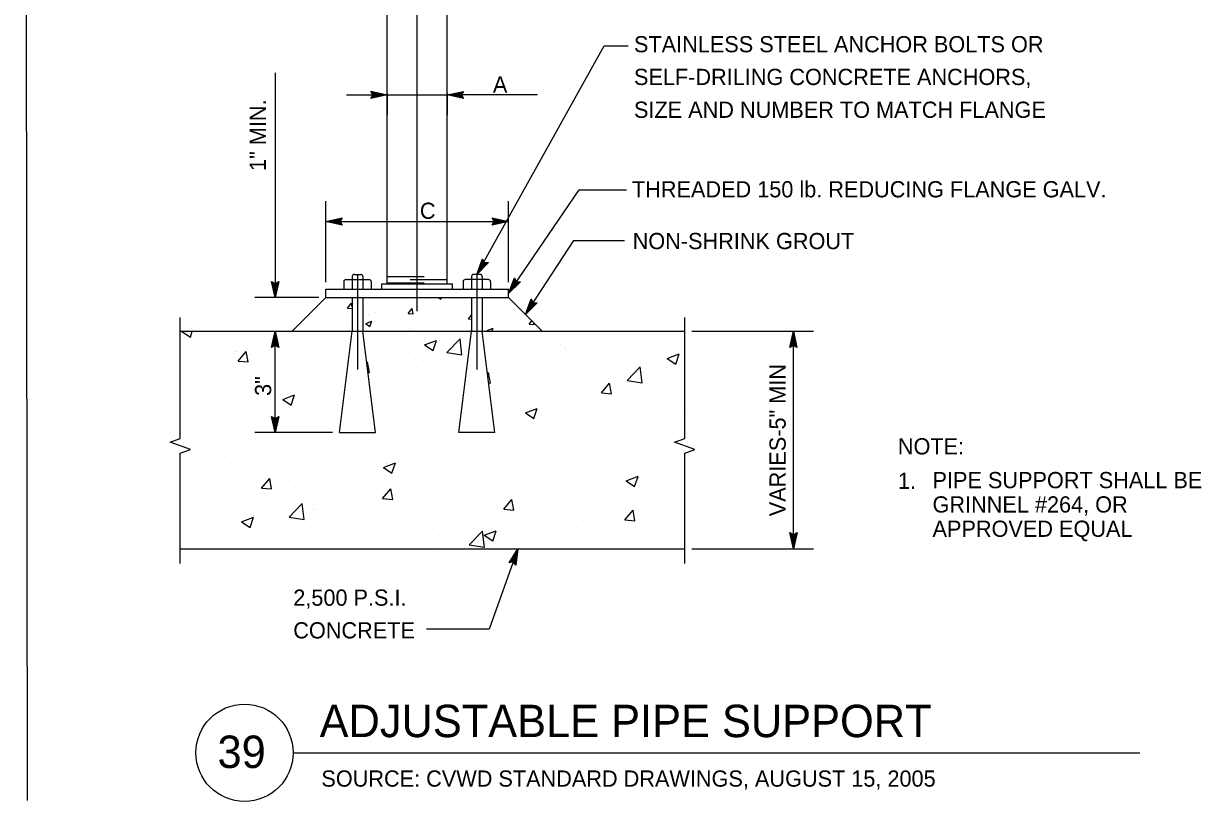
# Model space of a CAD drawing. Extents: x -121933 to -117742, y -103160 to -100084.
# Drawn here: x -121211 to -120775, y -102136.5 to -101848.5 of the extents above; entities that cross this region are included whole.
import ezdxf

# ---------------------------------------------------------------- set-up
doc = ezdxf.new("R2010")
doc.units = 0
for name, color, linetype in [('G-MARK', 7, 'Continuous'), ('G-TEXT', 7, 'Continuous'), ('Misc CnstDet(22)', 7, 'Continuous')]:
    doc.layers.add(name, color=color, linetype=linetype)

msp = doc.modelspace()

# ---------------------------------------------------------------- linework, layer by layer
at = {"layer": 'G-MARK'}
for p, q in [((-121117.88, -101866.71), (-121117.88, -101949.94)), ((-121091.47, -101874.94), (-121076.47, -101874.94)), ((-121020.77, -101874.94), (-121054.2, -101874.94)), ((-121099.13, -101944.19), (-121099.13, -101914.32)), ((-121031.55, -101944.19), (-121031.55, -101914.32)), ((-121099.13, -101921.82), (-121031.55, -101921.82)), ((-121101.75, -101949.94), (-121125.38, -101949.94)), ((-121117.88, -101999.94), (-121117.88, -101962.44)), ((-120963.69, -101962.44), (-120918.58, -101962.44)), ((-120926.08, -102042.91), (-120926.08, -101962.44)), ((-121096.67, -101999.94), (-121125.38, -101999.94)), ((-120963.69, -102042.91), (-120918.58, -102042.91))]:
    msp.add_line(p, q, dxfattribs=at)
for points in [[(-121043.27, -101941.35), (-120996.14, -101856.81), (-120987.23, -101856.81)], [(-121031.55, -101948.38), (-121005.38, -101910.1), (-120987.8, -101910.1)], [(-121025.3, -101956.19), (-121007.33, -101928.85), (-120988.58, -101928.85)], [(-121028.03, -102042.91), (-121038.74, -102072.63), (-121061.92, -102072.65)]]:
    msp.add_lwpolyline(points, dxfattribs=at)
at = {"layer": 'G-TEXT'}
for p, q in [((-121081.67, -101874.94), (-121082.47, -101873.6)), ((-121082.47, -101873.6), (-121082.47, -101873.6)), ((-121082.47, -101873.6), (-121076.47, -101874.94)), ((-121076.47, -101874.94), (-121082.47, -101876.27)), ((-121082.47, -101876.27), (-121081.67, -101874.94)), ((-121082.47, -101876.27), (-121082.47, -101876.27)), ((-121082.25, -101873.96), (-121077.85, -101874.94)), ((-121077.86, -101874.95), (-121082.24, -101875.91)), ((-121079.23, -101874.94), (-121082.06, -101875.57)), ((-121082.02, -101874.32), (-121079.23, -101874.94)), ((-121081.84, -101874.67), (-121080.61, -101874.94)), ((-121080.61, -101874.94), (-121081.82, -101875.21)), ((-121076.47, -101874.94), (-121076.47, -101874.94)), ((-121054.2, -101874.94), (-121048.2, -101873.61)), ((-121048.2, -101876.28), (-121054.2, -101874.94)), ((-121054.2, -101874.94), (-121054.2, -101874.94)), ((-121048.42, -101875.93), (-121052.82, -101874.94)), ((-121052.81, -101874.94), (-121048.44, -101873.97)), ((-121051.44, -101874.95), (-121048.62, -101874.32)), ((-121048.65, -101875.57), (-121051.44, -101874.95)), ((-121050.06, -101874.95), (-121048.85, -101874.68)), ((-121048.83, -101875.22), (-121050.06, -101874.95)), ((-121048.2, -101873.61), (-121049, -101874.94)), ((-121049, -101874.94), (-121048.2, -101876.28)), ((-121048.2, -101873.61), (-121048.2, -101873.61)), ((-121048.2, -101876.28), (-121048.2, -101876.28)), ((-121099.13, -101921.82), (-121093.13, -101920.49)), ((-121093.13, -101923.16), (-121099.13, -101921.82)), ((-121099.13, -101921.82), (-121099.13, -101921.82)), ((-121093.34, -101922.8), (-121097.75, -101921.82)), ((-121097.74, -101921.82), (-121093.36, -101920.85)), ((-121096.36, -101921.82), (-121093.54, -101921.19)), ((-121093.58, -101922.44), (-121096.36, -101921.82)), ((-121094.98, -101921.82), (-121093.77, -101921.55)), ((-121093.75, -101922.1), (-121094.98, -101921.82)), ((-121093.13, -101920.49), (-121093.93, -101921.82)), ((-121093.93, -101921.82), (-121093.13, -101923.16)), ((-121093.13, -101920.49), (-121093.13, -101920.49)), ((-121093.13, -101923.16), (-121093.13, -101923.16)), ((-121036.75, -101921.82), (-121037.55, -101920.48)), ((-121037.55, -101920.48), (-121037.55, -101920.48)), ((-121037.55, -101920.48), (-121031.55, -101921.82)), ((-121031.55, -101921.82), (-121037.55, -101923.15)), ((-121037.55, -101923.15), (-121036.75, -101921.82)), ((-121037.55, -101923.15), (-121037.55, -101923.15)), ((-121037.33, -101920.83), (-121032.93, -101921.82)), ((-121032.94, -101921.82), (-121037.31, -101922.79)), ((-121034.31, -101921.82), (-121037.14, -101922.44)), ((-121037.1, -101921.19), (-121034.31, -101921.82)), ((-121036.92, -101921.54), (-121035.69, -101921.82)), ((-121035.69, -101921.82), (-121036.9, -101922.08)), ((-121031.55, -101921.82), (-121031.55, -101921.82)), ((-121043.27, -101941.35), (-121041.17, -101935.57)), ((-121038.92, -101937.01), (-121043.27, -101941.35)), ((-121039.33, -101937), (-121042.53, -101940.19)), ((-121042.52, -101940.17), (-121040.99, -101935.96)), ((-121041.78, -101939.02), (-121040.8, -101936.3)), ((-121039.76, -101937), (-121041.78, -101939.02)), ((-121041.17, -101935.57), (-121041.17, -101935.57)), ((-121041.17, -101935.57), (-121040.48, -101936.96)), ((-121041.04, -101937.85), (-121040.62, -101936.69)), ((-121040.15, -101936.96), (-121041.04, -101937.85)), ((-121040.48, -101936.96), (-121038.92, -101937.01)), ((-121038.92, -101937.01), (-121038.92, -101937.01)), ((-121043.27, -101941.35), (-121043.27, -101941.35)), ((-121117.88, -101949.94), (-121119.21, -101943.94)), ((-121119.21, -101943.94), (-121119.21, -101943.94)), ((-121119.21, -101943.94), (-121117.88, -101944.74)), ((-121117.88, -101948.55), (-121118.85, -101944.18)), ((-121117.87, -101947.18), (-121118.5, -101944.36)), ((-121117.87, -101945.8), (-121118.14, -101944.59)), ((-121117.88, -101944.74), (-121116.54, -101943.94)), ((-121116.54, -101943.94), (-121117.88, -101949.94)), ((-121116.89, -101944.16), (-121117.88, -101948.56)), ((-121117.25, -101944.39), (-121117.87, -101947.18)), ((-121117.6, -101944.57), (-121117.87, -101945.8)), ((-121116.54, -101943.94), (-121116.54, -101943.94)), ((-121031.55, -101948.38), (-121029.26, -101942.68)), ((-121027.06, -101944.18), (-121031.55, -101948.38)), ((-121030.77, -101947.23), (-121029.1, -101943.07)), ((-121027.47, -101944.16), (-121030.77, -101947.24)), ((-121029.99, -101946.1), (-121028.91, -101943.42)), ((-121027.9, -101944.15), (-121029.99, -101946.1)), ((-121029.26, -101942.68), (-121029.26, -101942.68)), ((-121029.26, -101942.68), (-121028.61, -101944.09)), ((-121029.21, -101944.96), (-121028.75, -101943.81)), ((-121028.29, -101944.1), (-121029.21, -101944.96)), ((-121028.61, -101944.09), (-121027.06, -101944.18)), ((-121027.06, -101944.18), (-121027.06, -101944.18)), ((-121117.88, -101949.94), (-121117.88, -101949.94)), ((-121031.55, -101948.38), (-121031.55, -101948.38)), ((-121025.3, -101956.19), (-121023.14, -101950.44)), ((-121023.14, -101950.44), (-121023.14, -101950.44)), ((-121023.14, -101950.44), (-121022.46, -101951.84)), ((-121020.9, -101951.9), (-121025.3, -101956.19)), ((-121024.54, -101955.03), (-121022.97, -101950.83)), ((-121021.32, -101951.88), (-121024.54, -101955.04)), ((-121023.79, -101953.88), (-121022.77, -101951.17)), ((-121021.75, -101951.88), (-121023.79, -101953.88)), ((-121023.03, -101952.72), (-121022.6, -101951.56)), ((-121022.13, -101951.84), (-121023.03, -101952.72)), ((-121022.46, -101951.84), (-121020.9, -101951.9)), ((-121020.9, -101951.9), (-121020.9, -101951.9)), ((-121025.3, -101956.19), (-121025.3, -101956.19)), ((-121119.22, -101968.44), (-121117.88, -101962.44)), ((-121118.86, -101968.23), (-121117.88, -101963.82)), ((-121117.88, -101962.44), (-121117.88, -101962.44)), ((-121117.88, -101962.44), (-121116.55, -101968.44)), ((-121117.87, -101963.83), (-121116.91, -101968.21)), ((-120927.42, -101968.44), (-120926.08, -101962.44)), ((-120927.06, -101968.23), (-120926.08, -101963.82)), ((-120926.08, -101962.44), (-120926.08, -101962.44)), ((-120926.08, -101962.44), (-120924.75, -101968.44)), ((-120926.08, -101963.83), (-120925.11, -101968.21)), ((-121117.88, -101967.64), (-121119.22, -101968.44)), ((-121118.5, -101967.99), (-121117.88, -101965.21)), ((-121118.15, -101967.82), (-121117.88, -101966.59)), ((-121117.88, -101965.21), (-121117.25, -101968.03)), ((-121117.88, -101966.59), (-121117.61, -101967.8)), ((-121116.55, -101968.44), (-121117.88, -101967.64)), ((-120926.08, -101967.64), (-120927.42, -101968.44)), ((-120926.7, -101967.99), (-120926.08, -101965.21)), ((-120926.36, -101967.82), (-120926.08, -101966.59)), ((-120926.08, -101965.21), (-120925.46, -101968.03)), ((-120926.08, -101966.59), (-120925.81, -101967.8)), ((-120924.75, -101968.44), (-120926.08, -101967.64)), ((-121119.22, -101968.44), (-121119.22, -101968.44)), ((-121116.55, -101968.44), (-121116.55, -101968.44)), ((-120927.42, -101968.44), (-120927.42, -101968.44)), ((-120924.75, -101968.44), (-120924.75, -101968.44)), ((-121117.88, -101999.94), (-121119.21, -101993.94)), ((-121119.21, -101993.94), (-121119.21, -101993.94)), ((-121119.21, -101993.94), (-121117.88, -101994.74)), ((-121117.88, -101998.55), (-121118.85, -101994.18)), ((-121117.87, -101997.18), (-121118.5, -101994.36)), ((-121117.88, -101994.74), (-121116.54, -101993.94)), ((-121116.54, -101993.94), (-121117.88, -101999.94)), ((-121116.89, -101994.16), (-121117.88, -101998.56)), ((-121116.54, -101993.94), (-121116.54, -101993.94)), ((-121117.87, -101995.8), (-121118.14, -101994.59)), ((-121117.25, -101994.39), (-121117.87, -101997.18)), ((-121117.6, -101994.57), (-121117.87, -101995.8)), ((-121117.88, -101999.94), (-121117.88, -101999.94)), ((-120926.08, -102042.91), (-120927.41, -102036.91)), ((-120927.41, -102036.91), (-120927.41, -102036.91)), ((-120927.41, -102036.91), (-120926.08, -102037.71)), ((-120926.08, -102041.52), (-120927.05, -102037.15)), ((-120926.08, -102040.15), (-120926.7, -102037.32)), ((-120926.08, -102038.77), (-120926.34, -102037.56)), ((-120926.08, -102037.71), (-120924.74, -102036.91)), ((-120924.74, -102036.91), (-120926.08, -102042.91)), ((-120925.1, -102037.13), (-120926.08, -102041.53)), ((-120925.46, -102037.36), (-120926.08, -102040.15)), ((-120925.8, -102037.54), (-120926.08, -102038.77)), ((-120924.74, -102036.91), (-120924.74, -102036.91)), ((-121031.32, -102048.11), (-121028.03, -102042.91)), ((-121030.91, -102048.02), (-121028.5, -102044.21)), ((-121030.49, -102047.93), (-121028.97, -102045.51)), ((-121028.97, -102045.51), (-121029.33, -102048.38)), ((-121028.5, -102044.22), (-121029.07, -102048.67)), ((-121028.03, -102042.91), (-121028.81, -102049.01)), ((-121028.03, -102042.91), (-121028.03, -102042.91)), ((-120926.08, -102042.91), (-120926.08, -102042.91)), ((-121029.79, -102047.81), (-121031.32, -102048.11)), ((-121031.32, -102048.11), (-121031.32, -102048.11)), ((-121030.11, -102047.88), (-121029.44, -102046.81)), ((-121028.81, -102049.01), (-121029.79, -102047.81)), ((-121029.44, -102046.81), (-121029.59, -102048.04)), ((-121028.81, -102049.01), (-121028.81, -102049.01))]:
    msp.add_line(p, q, dxfattribs=at)
at = {"layer": 'Misc CnstDet(22)'}
for p, q in [((-121211.03, -101153.11), (-121209.67, -102136.14)), ((-121065.34, -101955.02), (-121065.34, -101695.26)), ((-121076.47, -101944.87), (-121076.47, -101832.76)), ((-121054.2, -101944.87), (-121054.2, -101832.76)), ((-121076.47, -101874.44), (-121076.47, -101882.44)), ((-121076.47, -101874.94), (-121054.2, -101874.94)), ((-121054.2, -101874.44), (-121054.2, -101882.44)), ((-121088.58, -101941.35), (-121086.24, -101941.35)), ((-121087.41, -101941.35), (-121087.41, -101976.51)), ((-121042.1, -101941.35), (-121044.44, -101941.35)), ((-121043.27, -101941.35), (-121043.27, -101976.51)), ((-121092.49, -101944.08), (-121092.49, -101946.82)), ((-121091.7, -101943.3), (-121083.11, -101943.3)), ((-121089.36, -101942.13), (-121089.36, -101946.82)), ((-121085.45, -101942.13), (-121085.45, -101946.82)), ((-121082.33, -101944.08), (-121082.33, -101946.82)), ((-121078.42, -101944.87), (-121052.25, -101944.87)), ((-121078.42, -101946.82), (-121078.42, -101944.87)), ((-121076.47, -101942.13), (-121062.8, -101942.13)), ((-121076.47, -101944.48), (-121062.8, -101944.48)), ((-121067.88, -101943.3), (-121054.2, -101943.3)), ((-121052.25, -101946.82), (-121052.25, -101944.87)), ((-121048.35, -101944.08), (-121048.35, -101946.82)), ((-121038.97, -101943.3), (-121047.56, -101943.3)), ((-121045.22, -101942.13), (-121045.22, -101946.82)), ((-121041.31, -101942.13), (-121041.31, -101946.82)), ((-121038.19, -101944.08), (-121038.19, -101946.82)), ((-121111.63, -101962.44), (-121099.13, -101949.94)), ((-121099.13, -101946.82), (-121031.55, -101946.82)), ((-121099.13, -101949.94), (-121099.13, -101946.82)), ((-121099.13, -101949.94), (-121031.55, -101949.94)), ((-121089.36, -101949.94), (-121089.36, -101962.44)), ((-121085.45, -101949.94), (-121085.45, -101962.44)), ((-121057.44, -101949.94), (-121056.55, -101950.54)), ((-121056.55, -101950.55), (-121056.34, -101949.94)), ((-121046.87, -101950.12), (-121046.87, -101950.12)), ((-121045.22, -101949.94), (-121045.22, -101962.44)), ((-121041.31, -101949.94), (-121041.31, -101962.44)), ((-121041.26, -101950.26), (-121041.26, -101950.26)), ((-121031.55, -101949.94), (-121031.55, -101946.82)), ((-121019.05, -101962.44), (-121031.55, -101949.94)), ((-121100.1, -101955.07), (-121100.1, -101955.07)), ((-121091.12, -101953.86), (-121089.61, -101952.07)), ((-121091.12, -101953.86), (-121089.36, -101954.02)), ((-121089.36, -101953.41), (-121089.61, -101952.07)), ((-121084.06, -101952.87), (-121084.06, -101952.87)), ((-121072.83, -101954.41), (-121072.83, -101954.41)), ((-121068.7, -101955.82), (-121067.19, -101954.03)), ((-121068.27, -101950.87), (-121068.27, -101950.87)), ((-121066.83, -101955.99), (-121067.19, -101954.03)), ((-121065.09, -101953.25), (-121065.09, -101953.25)), ((-121061, -101952.86), (-121061, -101952.86)), ((-121101.54, -101959.5), (-121101.54, -101959.5)), ((-121100.39, -101958.04), (-121100.39, -101958.04)), ((-121084.36, -101959.57), (-121082.17, -101958.73)), ((-121083.32, -101956.37), (-121083.32, -101956.37)), ((-121082.8, -101960.63), (-121082.17, -101958.74)), ((-121080.65, -101955.44), (-121080.65, -101955.44)), ((-121068.7, -101955.82), (-121066.83, -101955.99)), ((-121052.42, -101958.93), (-121052.42, -101958.93)), ((-121046.29, -101957.78), (-121045.22, -101956.51)), ((-121046.29, -101957.78), (-121045.22, -101957.88)), ((-121036.38, -101956.73), (-121036.38, -101956.73)), ((-121023.87, -101959.74), (-121022.9, -101958.59)), ((-121022, -101959.92), (-121022.1, -101959.39)), ((-121153.03, -101962.44), (-120966.31, -101962.44)), ((-121152.4, -101962.46), (-121152.36, -101962.44)), ((-121152.4, -101962.46), (-121149.29, -101964.56)), ((-121149.29, -101964.57), (-121148.58, -101962.44)), ((-121112.46, -101963.06), (-121112.46, -101963.06)), ((-121094.05, -101999.94), (-121089.36, -101962.44)), ((-121080.77, -101999.94), (-121085.45, -101962.44)), ((-121084.36, -101959.57), (-121082.81, -101960.62)), ((-121068.65, -101961.27), (-121068.65, -101961.27)), ((-121049.91, -101999.94), (-121045.22, -101962.44)), ((-121036.63, -101999.94), (-121041.31, -101962.44)), ((-121039.45, -101962.08), (-121037.26, -101961.24)), ((-121039.45, -101962.08), (-121038.9, -101962.44)), ((-121037.66, -101962.44), (-121037.26, -101961.24)), ((-121029.82, -101960), (-121029.82, -101960)), ((-121023.87, -101959.74), (-121022, -101959.91)), ((-121151.62, -101964.79), (-121151.62, -101964.79)), ((-121100.93, -101965.81), (-121100.93, -101965.81)), ((-121079.1, -101964.47), (-121079.1, -101964.47)), ((-121062.58, -101967.47), (-121058.21, -101965.79)), ((-121062.58, -101967.47), (-121059.47, -101969.56)), ((-121059.47, -101969.57), (-121058.2, -101965.79)), ((-121054.31, -101970.3), (-121049.45, -101965.23)), ((-121048.75, -101971.17), (-121049.44, -101965.24)), ((-121045.73, -101965.88), (-121045.73, -101965.88)), ((-121037.54, -101967.92), (-121037.54, -101967.92)), ((-121012.37, -101967.29), (-121012.37, -101967.29)), ((-120986.81, -101965.58), (-120986.81, -101965.58)), ((-121132.65, -101970.05), (-121132.65, -101970.05)), ((-121132.5, -101969.81), (-121132.5, -101969.81)), ((-121131.61, -101973.45), (-121128.6, -101969.85)), ((-121127.87, -101973.78), (-121128.59, -101969.86)), ((-121117.88, -101977.44), (-121117.88, -101969.94)), ((-121099.28, -101971.46), (-121099.28, -101971.46)), ((-121054.31, -101970.3), (-121048.75, -101971.17)), ((-121026.13, -101970.75), (-121026.13, -101970.75)), ((-121010.48, -101968.69), (-121010.48, -101968.69)), ((-120979.01, -101968.7), (-120979.01, -101968.7)), ((-120973.11, -101968.85), (-120973.11, -101968.85)), ((-120972.76, -101972.47), (-120968.38, -101970.79)), ((-120972.76, -101972.47), (-120969.65, -101974.57)), ((-120969.65, -101974.58), (-120968.38, -101970.8)), ((-121131.61, -101973.45), (-121127.87, -101973.77)), ((-121084, -101974.06), (-121083.77, -101973.78)), ((-121083.04, -101977.7), (-121083.77, -101973.78)), ((-121073.99, -101974.17), (-121073.99, -101974.17)), ((-121065.92, -101972.87), (-121065.92, -101972.87)), ((-121065.6, -101975.95), (-121065.6, -101975.95)), ((-121032.55, -101974.28), (-121032.55, -101974.28)), ((-121005.57, -101973.53), (-121005.57, -101973.53)), ((-120999.19, -101975.69), (-120999.19, -101975.69)), ((-120987.61, -101980.65), (-120982.74, -101975.57)), ((-120982.05, -101981.52), (-120982.74, -101975.58)), ((-121110.44, -101980.43), (-121110.44, -101980.43)), ((-121104.92, -101981.13), (-121104.92, -101981.13)), ((-121083.55, -101977.65), (-121083.04, -101977.69)), ((-121039.35, -101978.19), (-121038.94, -101977.7)), ((-121038.21, -101981.62), (-121038.94, -101977.71)), ((-121037.14, -101977.53), (-121037.14, -101977.53)), ((-120987.61, -101980.65), (-120982.05, -101981.51)), ((-121069.23, -101981.93), (-121069.23, -101981.93)), ((-121038.93, -101981.55), (-121038.22, -101981.62)), ((-120997.12, -101985.21), (-120994.11, -101981.62)), ((-120997.12, -101985.21), (-120993.39, -101985.54)), ((-120993.39, -101985.55), (-120994.11, -101981.63)), ((-121146.89, -101986.69), (-121146.89, -101986.69)), ((-121144.39, -101986.32), (-121144.39, -101986.32)), ((-121115.1, -101987.63), (-121110.72, -101985.95)), ((-121115.1, -101987.63), (-121111.99, -101989.72)), ((-121111.99, -101989.73), (-121110.72, -101985.95)), ((-121101.69, -101986.62), (-121101.69, -101986.62)), ((-120973.87, -101989.65), (-120973.87, -101989.65)), ((-121133.26, -101990.62), (-121133.26, -101990.62)), ((-121026.93, -101993.34), (-121026.93, -101993.34)), ((-121025.28, -101992.63), (-121020.9, -101990.95)), ((-121025.28, -101992.63), (-121022.17, -101994.73)), ((-121022.17, -101994.73), (-121020.9, -101990.96)), ((-121006.33, -101994.34), (-121006.33, -101994.34)), ((-121003.26, -101990.23), (-121003.26, -101990.23)), ((-120967.22, -101992.69), (-120967.22, -101992.69)), ((-121124.9, -101994.83), (-121124.9, -101994.83)), ((-121058.17, -101997.65), (-121058.17, -101997.65)), ((-121094.05, -101999.94), (-121080.77, -101999.94)), ((-121082.04, -102000.6), (-121082.04, -102000.6)), ((-121069.99, -102002.74), (-121069.99, -102002.74)), ((-121036.63, -101999.94), (-121049.91, -101999.94)), ((-121024.8, -101999.06), (-121024.8, -101999.06)), ((-121003.67, -101998.95), (-121003.67, -101998.95)), ((-120991.44, -102000.47), (-120991.44, -102000.47)), ((-121121.36, -102005.78), (-121121.36, -102005.78)), ((-121105.71, -102003.72), (-121105.71, -102003.72)), ((-121102.45, -102007.43), (-121102.45, -102007.43)), ((-121040.12, -102005.21), (-121040.12, -102005.21)), ((-121134.02, -102011.43), (-121134.02, -102011.43)), ((-121077.79, -102012.79), (-121073.41, -102011.11)), ((-121076.57, -102011.46), (-121076.57, -102011.46)), ((-121074.68, -102014.89), (-121073.41, -102011.12)), ((-120980.23, -102009.68), (-120980.23, -102009.68)), ((-120974.63, -102010.46), (-120974.63, -102010.46)), ((-121077.79, -102012.79), (-121074.68, -102014.89)), ((-121019.7, -102014.88), (-121019.7, -102014.88)), ((-121007.09, -102015.14), (-121007.09, -102015.14)), ((-120988.7, -102012.67), (-120988.7, -102012.67)), ((-120987.97, -102017.79), (-120983.59, -102016.11)), ((-120984.86, -102019.9), (-120983.59, -102016.12)), ((-121122.94, -102020.46), (-121119.92, -102016.87)), ((-121122.94, -102020.46), (-121119.2, -102020.78)), ((-121119.2, -102020.79), (-121119.92, -102016.87)), ((-121113.02, -102017.72), (-121113.02, -102017.72)), ((-121059.01, -102020.05), (-121059.01, -102020.05)), ((-121043.37, -102017.99), (-121043.37, -102017.99)), ((-121038.66, -102019.14), (-121038.66, -102019.14)), ((-121025.14, -102018.93), (-121025.14, -102018.93)), ((-120987.97, -102017.79), (-120984.86, -102019.89)), ((-121149.47, -102023.98), (-121149.47, -102023.98)), ((-121078.11, -102024.38), (-121075.09, -102020.79)), ((-121078.11, -102024.38), (-121074.37, -102024.71)), ((-121074.37, -102024.71), (-121075.09, -102020.8)), ((-121070.75, -102023.54), (-121070.75, -102023.54)), ((-121033.28, -102028.3), (-121030.27, -102024.71)), ((-121029.54, -102028.64), (-121030.26, -102024.72)), ((-121137.07, -102026.77), (-121137.07, -102026.77)), ((-121122.16, -102028.37), (-121122.16, -102028.37)), ((-121112.73, -102031.19), (-121107.86, -102026.11)), ((-121107.17, -102032.05), (-121107.86, -102026.12)), ((-121103.7, -102028.18), (-121103.7, -102028.18)), ((-121103.21, -102028.23), (-121103.21, -102028.23)), ((-121098.49, -102025.25), (-121098.49, -102025.25)), ((-121061.59, -102025.19), (-121061.59, -102025.19)), ((-121033.28, -102028.3), (-121029.54, -102028.63)), ((-120988.45, -102032.22), (-120985.44, -102028.63)), ((-120984.71, -102032.56), (-120985.44, -102028.64)), ((-121137.8, -102030.43), (-121137.8, -102030.43)), ((-121134.78, -102032.23), (-121134.78, -102032.23)), ((-121130.3, -102032.95), (-121125.93, -102031.27)), ((-121130.3, -102032.95), (-121127.19, -102035.04)), ((-121127.19, -102035.05), (-121125.93, -102031.27)), ((-121112.73, -102031.19), (-121107.17, -102032.05)), ((-121098.04, -102031.44), (-121098.04, -102031.44)), ((-121070.34, -102029.59), (-121070.34, -102029.59)), ((-121036.97, -102031), (-121036.97, -102031)), ((-121003.61, -102032.41), (-121003.61, -102032.41)), ((-120988.45, -102032.22), (-120984.71, -102032.55)), ((-120981.02, -102032.27), (-120981.02, -102032.27)), ((-120975.39, -102031.26), (-120975.39, -102031.26)), ((-121134.49, -102037.7), (-121134.49, -102037.7)), ((-121123.89, -102035.16), (-121123.89, -102035.16)), ((-121090.52, -102036.57), (-121090.52, -102036.57)), ((-121057.16, -102037.98), (-121057.16, -102037.98)), ((-121046.03, -102041.53), (-121041.16, -102036.46)), ((-121040.47, -102042.4), (-121041.16, -102036.46)), ((-121040.48, -102037.95), (-121036.11, -102036.27)), ((-121040.48, -102037.95), (-121037.37, -102040.05)), ((-121037.37, -102040.06), (-121036.11, -102036.28)), ((-121007.85, -102035.95), (-121007.85, -102035.95)), ((-120996.67, -102034.33), (-120996.67, -102034.33)), ((-120970.25, -102033.82), (-120970.25, -102033.82)), ((-121046.03, -102041.53), (-121040.47, -102042.39)), ((-121039.42, -102039.95), (-121039.42, -102039.95)), ((-121036.14, -102039.53), (-121036.14, -102039.53)), ((-121023.8, -102039.39), (-121023.8, -102039.39)), ((-121001.28, -102040.8), (-121001.28, -102040.8)), ((-120990.43, -102040.8), (-120990.43, -102040.8)), ((-121153.03, -102042.91), (-120966.31, -102042.91)), ((-121059.81, -102042.64), (-121059.81, -102042.64)), ((-121111.24, -102118.45), (-120797.79, -102118.45))]:
    msp.add_line(p, q, dxfattribs=at)
for points in [[(-121153.03, -102048.38), (-121153.03, -102007.54), (-121149.28, -102006.17), (-121156.79, -102003.44), (-121153.03, -102002.07), (-121153.03, -101957.37)], [(-120966.31, -102048.38), (-120966.31, -102007.54), (-120962.56, -102006.17), (-120970.07, -102003.44), (-120966.31, -102002.07), (-120966.31, -101957.37)]]:
    msp.add_lwpolyline(points, dxfattribs=at)
msp.add_circle((-121129.24, -102118.45), 18, dxfattribs=at)
for centre, start, end in [((-121088.58, -101942.13), 90, 180), ((-121086.24, -101942.13), 0, 90), ((-121044.44, -101942.13), 90, 180), ((-121042.1, -101942.13), 0, 90), ((-121091.7, -101944.08), 90, 180), ((-121083.11, -101944.08), 0, 90), ((-121047.56, -101944.08), 90, 180), ((-121038.97, -101944.08), 0, 90)]:
    msp.add_arc(centre, 0.781, start, end, dxfattribs=at)

# ---------------------------------------------------------------- texts
for s, height, p in [('STAINLESS STEEL ANCHOR BOLTS OR', 6, (-120985.09, -101859.16)), ('SELF-DRILING CONCRETE ANCHORS,', 6, (-120985.09, -101871.27)), ('A', 6, (-121037.31, -101874.08)), ('SIZE AND NUMBER TO MATCH FLANGE', 6, (-120985.09, -101883.42)), ('THREADED 150 lb. REDUCING FLANGE GALV.', 6, (-120985.84, -101912.86)), ('C', 6, (-121064.33, -101920.8)), ('NON-SHRINK GROUT', 6, (-120985.57, -101932.02)), ('NOTE:', 6, (-120887.41, -102008)), ('1.', 6, (-120887.41, -102020.77)), ('PIPE SUPPORT SHALL BE', 6, (-120874.58, -102020.51)), ('GRINNEL #264, OR', 6, (-120874.58, -102029.51)), ('APPROVED EQUAL', 6, (-120874.58, -102038.51)), ('2,500 P.S.I.', 6, (-121111.2, -102064.01)), ('CONCRETE', 6, (-121111.2, -102076.12)), ('ADJUSTABLE PIPE SUPPORT', 12, (-121101.44, -102112.66)), ('39', 12, (-121139.23, -102124.07)), ('SOURCE: CVWD STANDARD DRAWINGS, AUGUST 15, 2005', 6, (-121100.79, -102130.98))]:
    msp.add_text(s, height=height, dxfattribs=at).set_placement(p)
for s, p in [('1" MIN.', (-121121.33, -101903.07)), ('VARIES-5" MIN', (-120928.93, -102030.89)), ('3"', (-121119.37, -101986.35))]:
    msp.add_text(s, height=6, rotation=90, dxfattribs=at).set_placement(p)

doc.saveas('drawing.dxf')
